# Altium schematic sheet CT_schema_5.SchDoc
size 520 x 457 mm
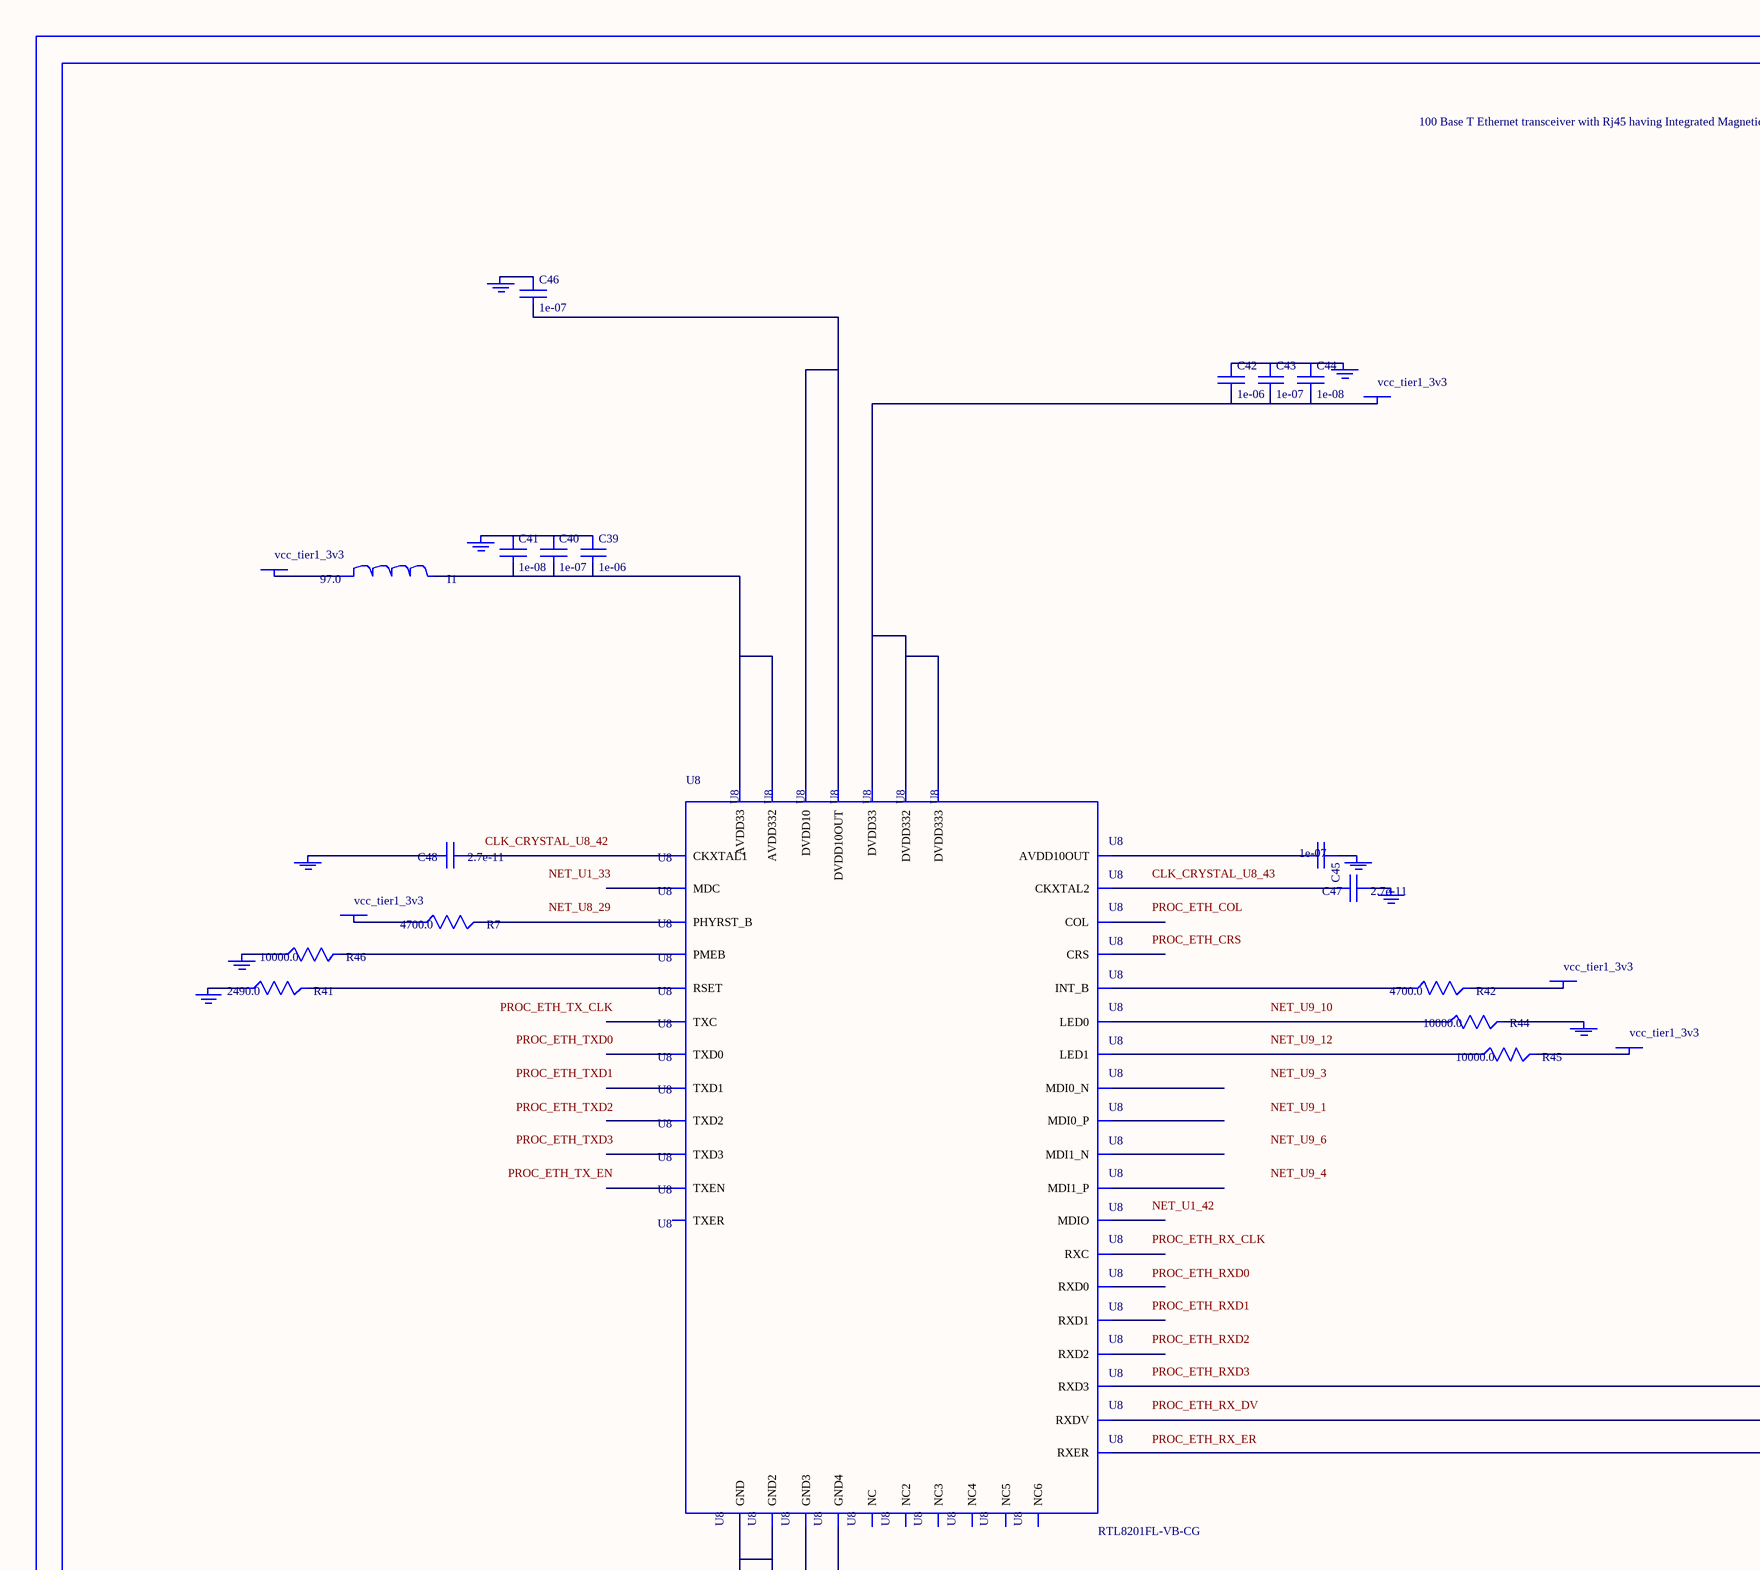
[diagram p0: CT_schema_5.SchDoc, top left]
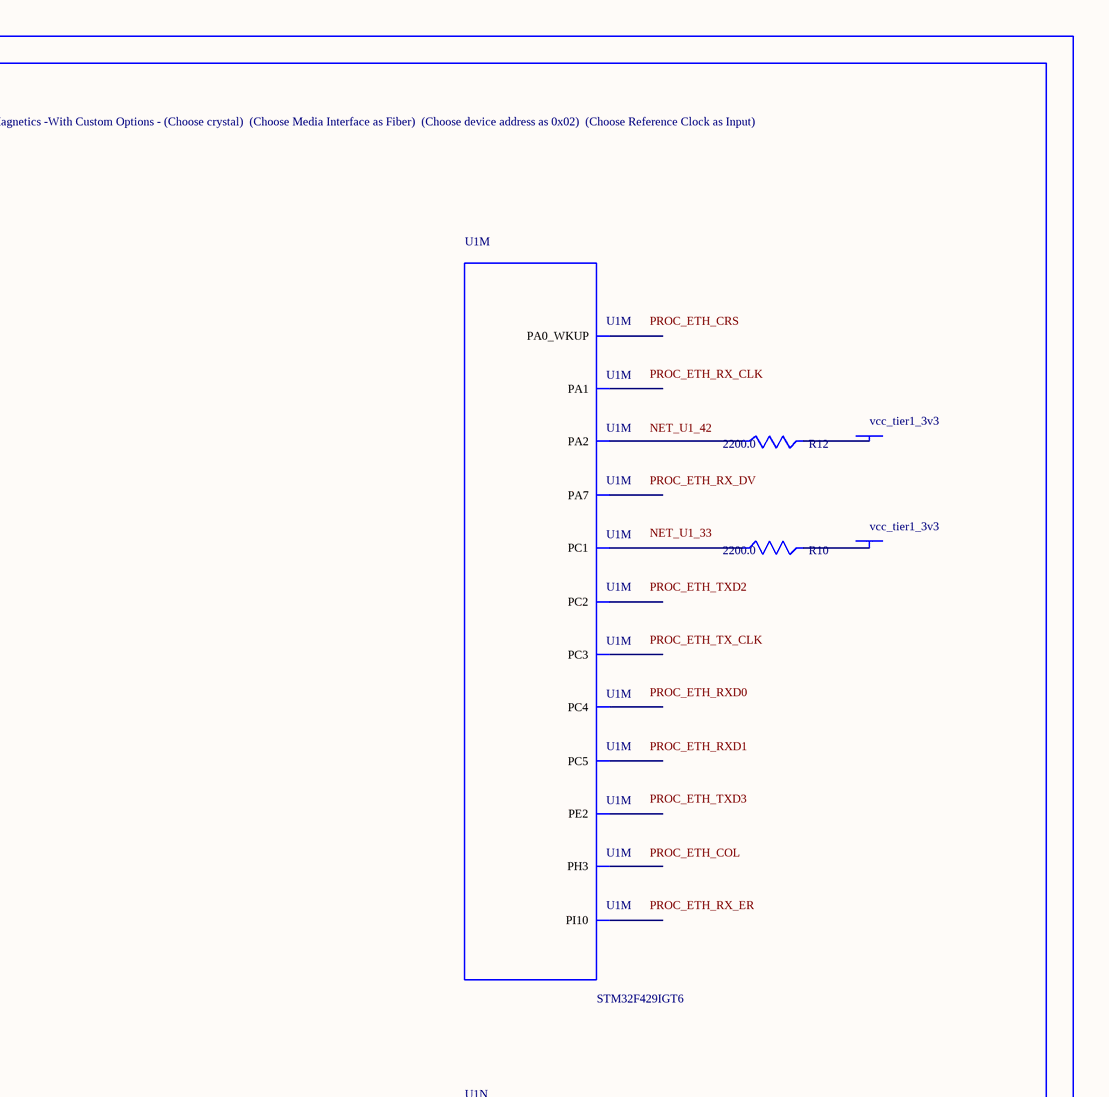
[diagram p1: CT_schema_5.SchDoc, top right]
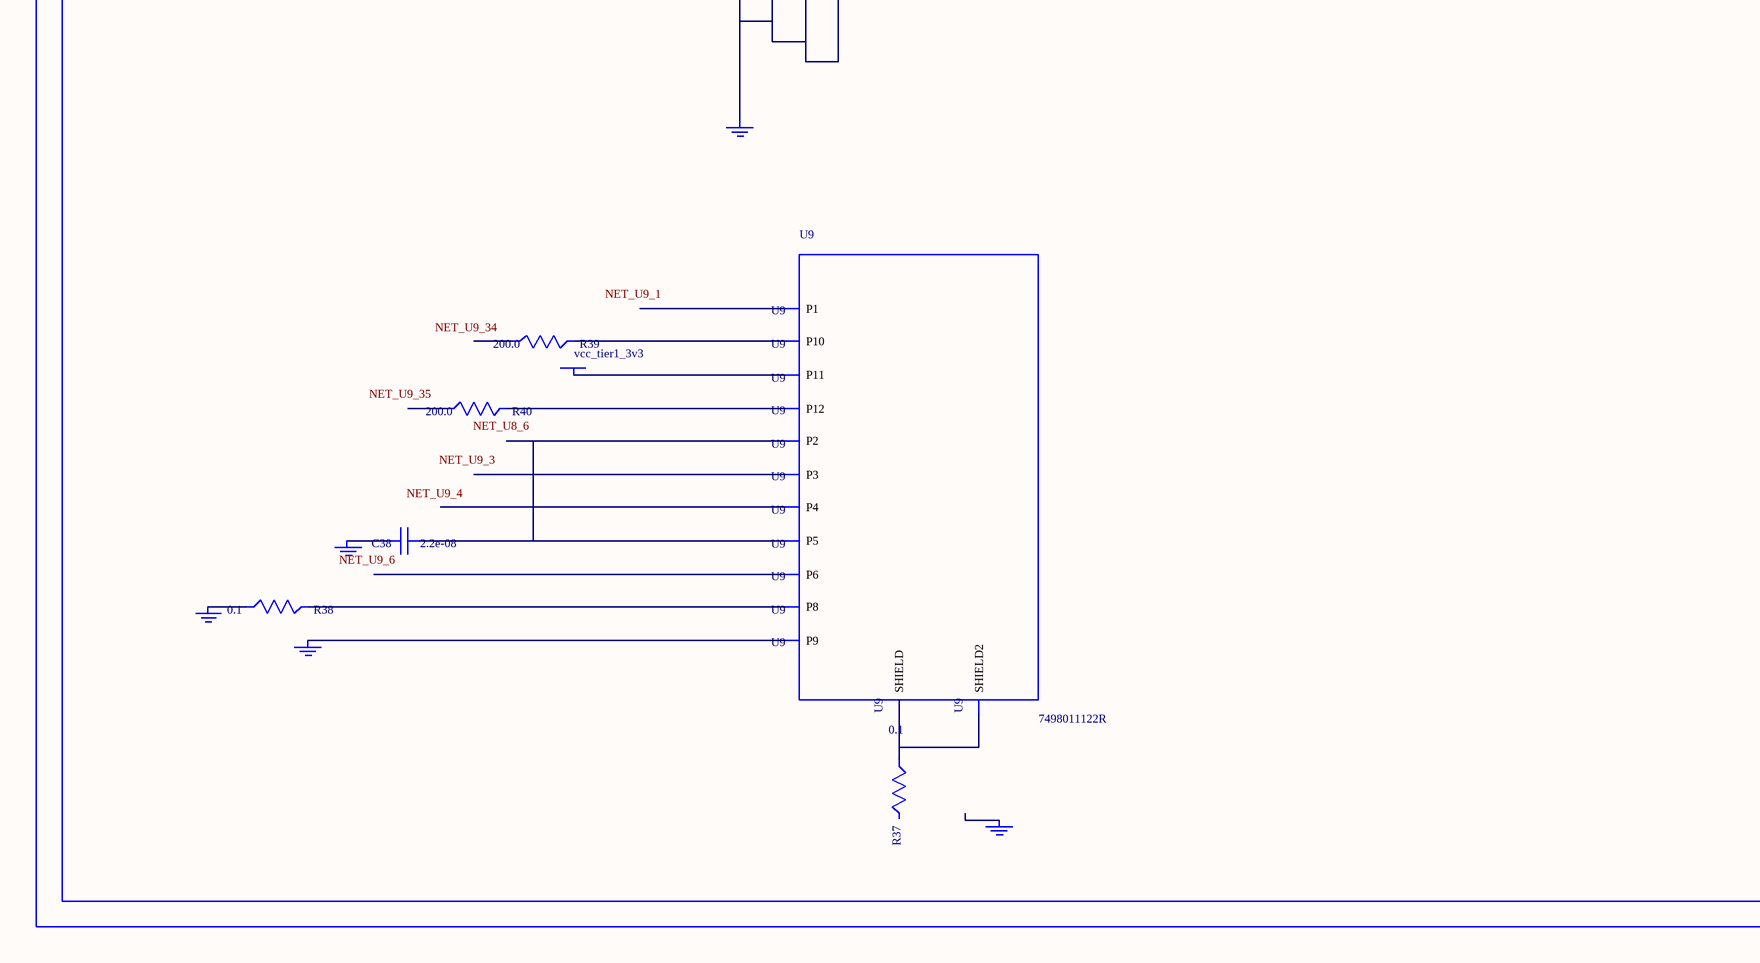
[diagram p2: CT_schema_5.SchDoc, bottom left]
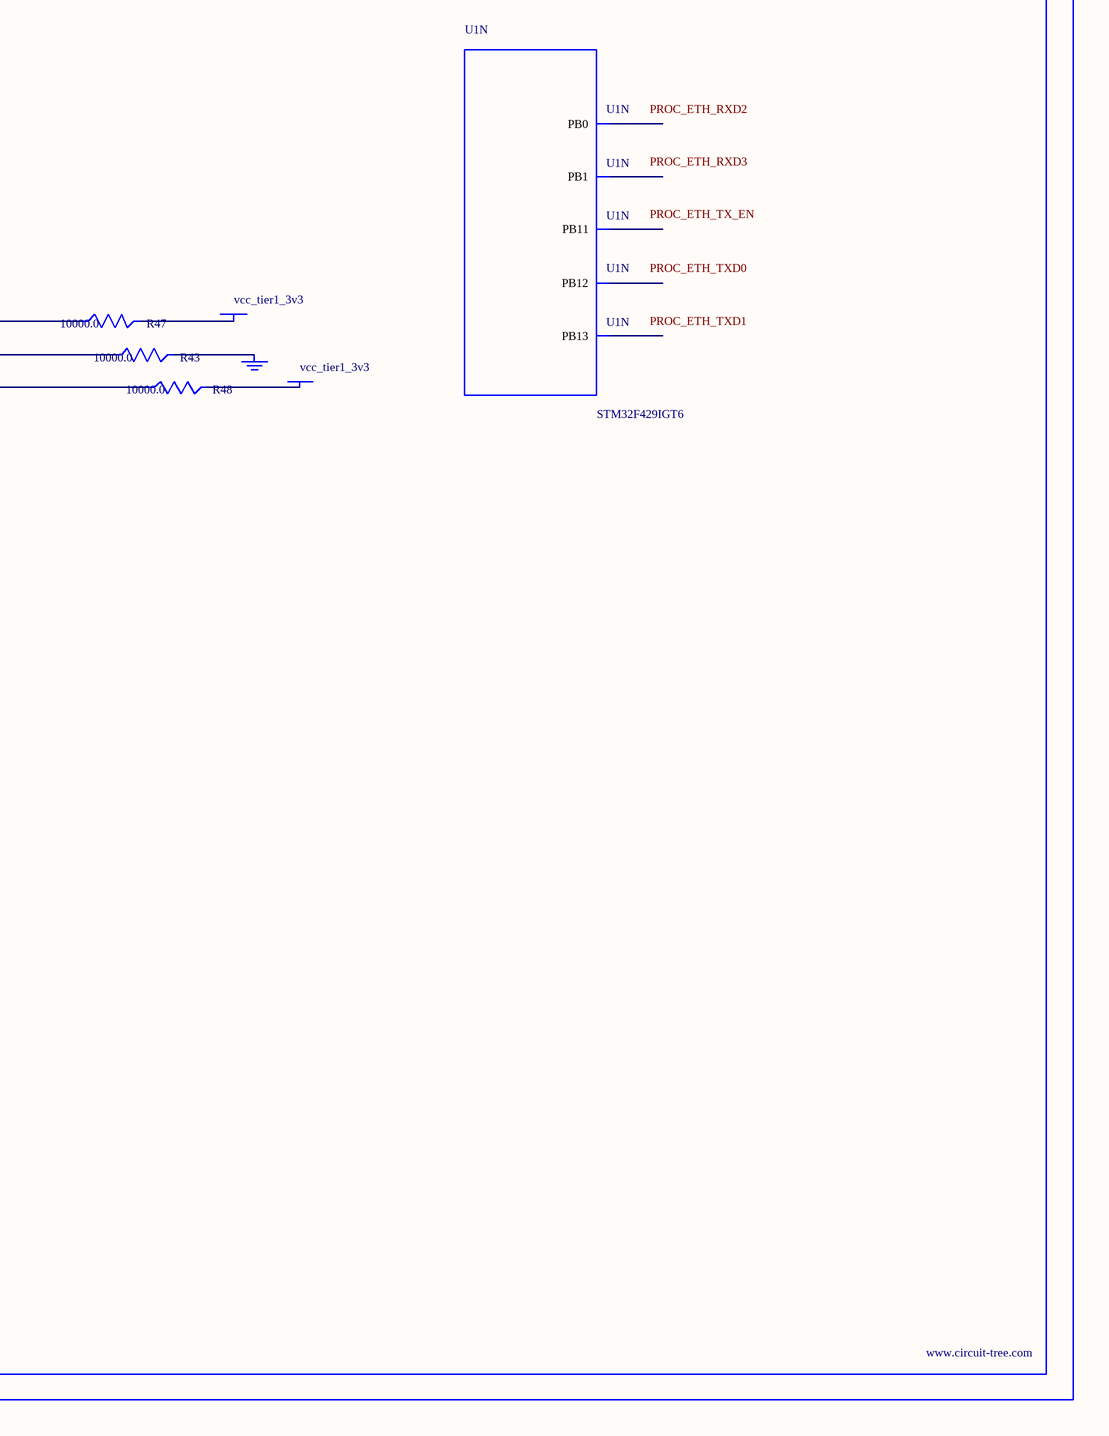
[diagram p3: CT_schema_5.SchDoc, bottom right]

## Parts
BORDER4  (no value)
C38  2.2e-08  [C0402]
C39  1e-06  [C0603]
C40  1e-07  [C0402]
C41  1e-08  [C0402]
C42  1e-06  [C0603]
C43  1e-07  [C0402]
C44  1e-08  [C0402]
C45  1e-07  [C0402]
C46  1e-07  [C0402]
C47  2.7e-11  [C0402]
C48  2.7e-11  [C0402]
GND_INSTANCE_4_0  (no value)
GND_INSTANCE_4_1  (no value)
GND_INSTANCE_4_2  (no value)
GND_INSTANCE_4_3  (no value)
GND_INSTANCE_4_4  (no value)
GND_INSTANCE_4_5  (no value)
GND_INSTANCE_4_6  (no value)
GND_INSTANCE_4_7  (no value)
GND_INSTANCE_4_8  (no value)
GND_INSTANCE_4_9  (no value)
GND_INSTANCE_4_10  (no value)
GND_INSTANCE_4_11  (no value)
GND_INSTANCE_4_12  (no value)
GND_INSTANCE_4_13  (no value)
GND_INSTANCE_4_14  (no value)
I1  97.0  [R0603]
POWER_INSTANCE_4_0  vcc_tier1_3v3
POWER_INSTANCE_4_1  vcc_tier1_3v3
POWER_INSTANCE_4_2  vcc_tier1_3v3
POWER_INSTANCE_4_3  vcc_tier1_3v3
POWER_INSTANCE_4_4  vcc_tier1_3v3
POWER_INSTANCE_4_5  vcc_tier1_3v3
POWER_INSTANCE_4_6  vcc_tier1_3v3
POWER_INSTANCE_4_7  vcc_tier1_3v3
POWER_INSTANCE_4_8  vcc_tier1_3v3
POWER_INSTANCE_4_9  vcc_tier1_3v3
R7  4700.0  [R0603]
R10  2200.0  [R0603]
R12  2200.0  [R0603]
R37  0.1  [R0603]
R38  0.1  [R0603]
R39  200.0  [R0603]
R40  200.0  [R0603]
R41  2490.0  [R0603]
R42  4700.0  [R0603]
R43  10000.0  [R0603]
R44  10000.0  [R0603]
R45  10000.0  [R0603]
R46  10000.0  [R0603]
R47  10000.0  [R0603]
R48  10000.0  [R0603]
U1  STM32F429IGT6  [LQFP176]  (parts M,N of 15)
U8  RTL8201FL-VB-CG  [RTL8201FL-VB-CG]
U9  7498011122R  [7498011122R]

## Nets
NetC38_1: C38.1 U9.2(P2) U9.5(P5)
NetC38_2: C38.2 GND_INSTANCE_4_11.0(GND)
NetC39_1: C39.1 C40.1 C41.1 GND_INSTANCE_4_0.0(GND)
NetC39_2: C39.2 C40.2 C41.2 I1.2 U8.6(AVDD33) U8.41(AVDD332)
NetC42_1: C42.1 C43.1 C44.1 GND_INSTANCE_4_3.0(GND)
NetC42_2: C42.2 C43.2 C44.2 POWER_INSTANCE_4_1.0(PWR) U8.15(DVDD33) U8.21(DVDD332) U8.37(DVDD333)
NetC45_1: C45.1 GND_INSTANCE_4_9.0(GND)
NetC45_2: C45.2 U8.48(AVDD10OUT)
NetC46_1: C46.1 GND_INSTANCE_4_5.0(GND)
NetC46_2: C46.2 U8.28(DVDD10) U8.40(DVDD10OUT)
NetC47_1: C47.1 GND_INSTANCE_4_7.0(GND)
NetC47_2: C47.2 U8.43(CKXTAL2)
NetC48_1: C48.1 U8.42(CKXTAL1)
NetC48_2: C48.2 GND_INSTANCE_4_6.0(GND)
NetGND_INSTANCE_4_1_0: GND_INSTANCE_4_1.0(GND) R46.1
NetGND_INSTANCE_4_2_0: GND_INSTANCE_4_2.0(GND) R43.2
NetGND_INSTANCE_4_4_0: GND_INSTANCE_4_4.0(GND) R44.2
NetGND_INSTANCE_4_8_0: GND_INSTANCE_4_8.0(GND) R41.1
NetGND_INSTANCE_4_10_0: GND_INSTANCE_4_10.0(GND) U8.7(GND) U8.20(GND2) U8.33(GND3) U8.47(GND4)
NetGND_INSTANCE_4_12_0: GND_INSTANCE_4_12.0(GND) R38.1
NetGND_INSTANCE_4_13_0: GND_INSTANCE_4_13.0(GND) U9.9(P9)
NetI1_1: I1.1 POWER_INSTANCE_4_0.0(PWR)
NetPOWER_INSTANCE_4_2_0: POWER_INSTANCE_4_2.0(PWR) R47.2
NetPOWER_INSTANCE_4_3_0: POWER_INSTANCE_4_3.0(PWR) R42.2
NetPOWER_INSTANCE_4_4_0: POWER_INSTANCE_4_4.0(PWR) R45.2
NetPOWER_INSTANCE_4_5_0: POWER_INSTANCE_4_5.0(PWR) R48.2
NetPOWER_INSTANCE_4_6_0: POWER_INSTANCE_4_6.0(PWR) R7.1
NetPOWER_INSTANCE_4_7_0: POWER_INSTANCE_4_7.0(PWR) R10.2
NetPOWER_INSTANCE_4_8_0: POWER_INSTANCE_4_8.0(PWR) R12.2
NetPOWER_INSTANCE_4_9_0: POWER_INSTANCE_4_9.0(PWR) U9.11(P11)
NetR7_2: R7.2 U8.29(PHYRST_B)
NetR10_1: R10.1 U1.33(PC1)
NetR12_1: R12.1 U1.42(PA2)
NetR37_1: R37.1 U9.13(SHIELD) U9.14(SHIELD2)
NetR38_2: R38.2 U9.8(P8)
NetR39_2: R39.2 U9.10(P10)
NetR40_2: R40.2 U9.12(P12)
NetR41_2: R41.2 U8.46(RSET)
NetR42_1: R42.1 U8.32(INT_B)
NetR43_1: R43.1 U8.13(RXDV)
NetR44_1: R44.1 U8.34(LED0)
NetR45_1: R45.1 U8.35(LED1)
NetR46_2: R46.2 U8.10(PMEB)
NetR47_1: R47.1 U8.18(RXD3)
NetR48_1: R48.1 U8.39(RXER)

Not connected (* = marked no-connect by the designer): GND_INSTANCE_4_14 0(GND); R37 2; R39 1; R40 1; U1 1(PE2) 12(PI10) 34(PC2) 35(PC3) 40(PA0_WKUP) 41(PA1) 44(PH3) 53(PA7) 54(PC4) 55(PC5) 56(PB0) 57(PB1) 80(PB11) 92(PB12) 93(PB13); U8 1(MDI0_P) 2(MDI0_N) 3(NC) 4(MDI1_P) 5(MDI1_N) 8(NC2) 9(NC3) 11(NC4) 12(TXER) 14(RXD0) 16(RXD1) 17(RXD2) 19(RXC) 22(TXC) 23(TXD0) 24(TXD1) 25(TXD2) 26(TXD3) 27(TXEN) 30(MDC) 31(MDIO) 36(CRS) 38(COL) 44(NC5) 45(NC6); U9 1(P1) 3(P3) 4(P4) 6(P6)

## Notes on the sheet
- Labels drawn without touching a wire or pin: CLK_CRYSTAL_U8_42, CLK_CRYSTAL_U8_43, NET_U1_33, NET_U1_42, NET_U8_6, NET_U8_29, NET_U9_1, NET_U9_3, NET_U9_4, NET_U9_6, NET_U9_10, NET_U9_12, NET_U9_34, NET_U9_35, PROC_ETH_COL, PROC_ETH_CRS, PROC_ETH_RX_CLK, PROC_ETH_RX_DV, PROC_ETH_RX_ER, PROC_ETH_RXD0, PROC_ETH_RXD1, PROC_ETH_RXD2, PROC_ETH_RXD3, PROC_ETH_TX_CLK, PROC_ETH_TX_EN, PROC_ETH_TXD0, PROC_ETH_TXD1, PROC_ETH_TXD2, PROC_ETH_TXD3

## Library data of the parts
BORDER4 = BORDER_PAGE4
C38 = C0402C223K3RAC
C39 C42 = C0603C105K3RACTU
C40 C43 C45 C46 = C0402C104K3RACTU
C41 C44 = C0402C103K3RAC
C47 C48 = C0402C270K3RAC
GND_INSTANCE_4_0-GND_INSTANCE_4_14 = GND
I1 = I1
POWER_INSTANCE_4_0-POWER_INSTANCE_4_9 = PWR
R7 R42 = RC0603JR-074K7L
R10 R12 = RC0603JR-072K2L
R37 R38 = ERJ-3RSFR10V
R39 R40 = RC0603JR-07200RL
R41 = ERA-3AED2490V
R43-R48 = RC0603JR-0710KL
